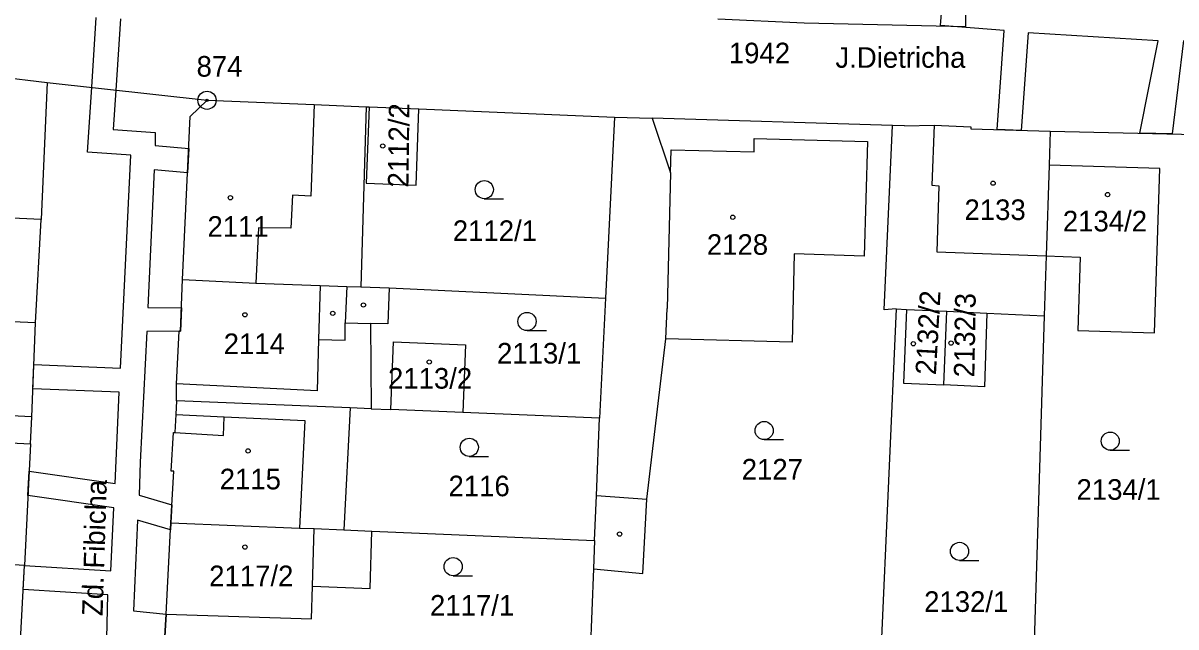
# Model space of a CAD drawing. Extents: x -755819 to -753140, y -1169796 to -1166000.
# Drawn here: x -755181.4 to -755086.2, y -1168037.7 to -1167987.9 of the extents above; entities that cross this region are included whole.
import ezdxf

# ---------------------------------------------------------------- set-up
doc = ezdxf.new("R2010")
doc.units = 0
for name, color, linetype in [('Vrstva 1', 7, 'Continuous'), ('Vrstva 15', 7, 'Continuous'), ('Vrstva 17', 7, 'Continuous'), ('Vrstva 18', 7, 'Continuous'), ('Vrstva 19', 7, 'Continuous'), ('Vrstva 24', 7, 'Continuous'), ('Vrstva 25', 7, 'Continuous'), ('Vrstva 27', 7, 'Continuous'), ('Vrstva 4', 7, 'Continuous')]:
    doc.layers.add(name, color=color, linetype=linetype)

msp = doc.modelspace()

# ---------------------------------------------------------------- linework, layer by layer
at = {"layer": 'Vrstva 1'}
for p, q in [((-755201.7, -1167990.2), (-755179.37, -1167992.78)), ((-755179.37, -1167992.78), (-755179.86, -1168004.09)), ((-755179.37, -1167992.78), (-755166.17, -1167994.26)), ((-755167.56, -1167995.59), (-755166.17, -1167994.26)), ((-755166.17, -1167994.26), (-755157.33, -1167994.61)), ((-755157.33, -1167994.61), (-755153.04, -1167994.79)), ((-755153.04, -1167994.79), (-755153.48, -1168009.65)), ((-755153.04, -1167994.79), (-755152.79, -1167994.8)), ((-755152.79, -1167994.8), (-755153.03, -1168001.11)), ((-755152.79, -1167994.8), (-755148.67, -1167994.97)), ((-755148.91, -1168001.27), (-755148.67, -1167994.97)), ((-755148.67, -1167994.97), (-755132.53, -1167995.65)), ((-755168.19, -1168009.04), (-755167.56, -1167995.59)), ((-755132.53, -1167995.65), (-755133.27, -1168010.58)), ((-755132.53, -1167995.65), (-755129.41, -1167995.74)), ((-755109.58, -1167996.35), (-755129.41, -1167995.74)), ((-755129.41, -1167995.74), (-755127.9, -1168000.25)), ((-755110.26, -1168011.56), (-755109.58, -1167996.35)), ((-755108.58, -1167996.38), (-755109.58, -1167996.35)), ((-755108.58, -1167996.38), (-755106.13, -1167996.31)), ((-755106.13, -1167996.31), (-755103.11, -1167996.46)), ((-755103.11, -1167996.46), (-755103.12, -1167996.61)), ((-755103.12, -1167996.61), (-755096.55, -1167996.81)), ((-755096.55, -1167996.81), (-755096.64, -1167999.6)), ((-755096.55, -1167996.81), (-755084.51, -1167997.07)), ((-755121, -1167998.52), (-755121, -1167997.4)), ((-755121, -1167997.4), (-755111.63, -1167997.67)), ((-755111.63, -1167997.67), (-755111.92, -1168007.11)), ((-755127.9, -1168000.25), (-755127.85, -1167998.34)), ((-755127.85, -1167998.34), (-755121, -1167998.52)), ((-755096.64, -1167999.6), (-755096.9, -1168007.1)), ((-755087.5, -1167999.9), (-755096.64, -1167999.6)), ((-755087.95, -1168013.46), (-755087.5, -1167999.9)), ((-755153.03, -1168001.11), (-755148.91, -1168001.27)), ((-755179.86, -1168004.09), (-755190.56, -1168003.61)), ((-755180.34, -1168012.62), (-755179.86, -1168004.09)), ((-755117.69, -1168006.93), (-755117.81, -1168011.73)), ((-755111.92, -1168007.11), (-755117.69, -1168006.93)), ((-755096.9, -1168007.1), (-755097.05, -1168012.04)), ((-755096.9, -1168007.1), (-755094.07, -1168007.19)), ((-755094.07, -1168007.19), (-755094.27, -1168013.25)), ((-755168.35, -1168013.31), (-755168.19, -1168009.04)), ((-755168.19, -1168009.04), (-755162.15, -1168009.34)), ((-755162.15, -1168009.34), (-755156.83, -1168009.53)), ((-755156.83, -1168009.53), (-755154.63, -1168009.62)), ((-755154.63, -1168009.62), (-755153.48, -1168009.65)), ((-755153.48, -1168009.65), (-755151.14, -1168009.73)), ((-755151.14, -1168009.73), (-755151.24, -1168012.71)), ((-755151.14, -1168009.73), (-755133.27, -1168010.58)), ((-755133.27, -1168010.58), (-755133.76, -1168020.48)), ((-755109.26, -1168011.47), (-755110.63, -1168041.69)), ((-755109.26, -1168011.47), (-755110.26, -1168011.56)), ((-755109.26, -1168011.47), (-755108.42, -1168011.51)), ((-755108.42, -1168011.51), (-755108.68, -1168017.61)), ((-755108.42, -1168011.51), (-755105.1, -1168011.66)), ((-755105.33, -1168017.75), (-755105.1, -1168011.66)), ((-755105.1, -1168011.66), (-755101.78, -1168011.82)), ((-755180.34, -1168012.62), (-755188.32, -1168012.28)), ((-755117.81, -1168011.73), (-755117.87, -1168014.23)), ((-755101.78, -1168011.82), (-755101.99, -1168017.89)), ((-755101.78, -1168011.82), (-755097.05, -1168012.04)), ((-755097.05, -1168012.04), (-755097.97, -1168042.2)), ((-755180.63, -1168020.37), (-755180.34, -1168012.62)), ((-755168.68, -1168017.65), (-755168.48, -1168013.31)), ((-755168.48, -1168013.31), (-755168.35, -1168013.31)), ((-755151.24, -1168012.71), (-755152.68, -1168012.67)), ((-755152.68, -1168012.67), (-755152.61, -1168019.71)), ((-755094.27, -1168013.25), (-755087.95, -1168013.46)), ((-755150.99, -1168019.77), (-755150.77, -1168014.19)), ((-755150.77, -1168014.19), (-755144.84, -1168014.43)), ((-755144.84, -1168014.43), (-755145.06, -1168020.01)), ((-755129.86, -1168027.18), (-755128.3, -1168013.95)), ((-755117.87, -1168014.23), (-755128.3, -1168013.95)), ((-755168.69, -1168019.05), (-755168.68, -1168017.65)), ((-755108.68, -1168017.61), (-755105.33, -1168017.75)), ((-755101.99, -1168017.89), (-755105.33, -1168017.75)), ((-755168.69, -1168019.05), (-755168.75, -1168020.19)), ((-755154.35, -1168019.64), (-755168.69, -1168019.05)), ((-755168.75, -1168020.19), (-755168.84, -1168021.67)), ((-755154.35, -1168019.64), (-755154.87, -1168029.71)), ((-755152.61, -1168019.71), (-755154.35, -1168019.64)), ((-755152.61, -1168019.71), (-755150.99, -1168019.77)), ((-755145.06, -1168020.01), (-755150.99, -1168019.77)), ((-755133.76, -1168020.48), (-755145.06, -1168020.01)), ((-755180.75, -1168022.61), (-755180.63, -1168020.37)), ((-755134.02, -1168026.88), (-755133.76, -1168020.48)), ((-755191.56, -1168022.09), (-755180.75, -1168022.61)), ((-755169.14, -1168024.85), (-755168.95, -1168021.67)), ((-755168.95, -1168021.67), (-755168.84, -1168021.67)), ((-755180.75, -1168022.61), (-755181.25, -1168032.65)), ((-755169.15, -1168029.11), (-755168.92, -1168024.85)), ((-755168.92, -1168024.85), (-755169.14, -1168024.85)), ((-755134.17, -1168030.57), (-755134.02, -1168026.88)), ((-755130.2, -1168033.31), (-755129.86, -1168027.18)), ((-755169.55, -1168036.67), (-755169.15, -1168029.11)), ((-755169.15, -1168029.11), (-755158.53, -1168029.55)), ((-755158.53, -1168029.55), (-755157.33, -1168029.6)), ((-755157.47, -1168034.35), (-755157.33, -1168029.6)), ((-755157.33, -1168029.6), (-755154.87, -1168029.71)), ((-755154.87, -1168029.71), (-755152.55, -1168029.8)), ((-755152.55, -1168029.8), (-755134.17, -1168030.57)), ((-755134.17, -1168030.57), (-755134.26, -1168032.92)), ((-755181.25, -1168032.65), (-755191.89, -1168031.99)), ((-755181.76, -1168042.63), (-755181.25, -1168032.65)), ((-755134.26, -1168032.92), (-755134.57, -1168040.46)), ((-755134.26, -1168032.92), (-755130.2, -1168033.31)), ((-755157.54, -1168037.03), (-755157.47, -1168034.35)), ((-755169.67, -1168038.95), (-755169.55, -1168036.67)), ((-755169.55, -1168036.67), (-755157.54, -1168037.03))]:
    msp.add_line(p, q, dxfattribs=at)
at = {"layer": 'Vrstva 24'}
for radius in [0.75, 0.1]:
    msp.add_circle((-755166.17, -1167994.26), radius, dxfattribs=at)
at = {"layer": 'Vrstva 25'}
for p, q in [((-755143.28, -1168002.38), (-755141.68, -1168002.38)), ((-755139.75, -1168013.26), (-755138.15, -1168013.26)), ((-755120.17, -1168022.26), (-755118.57, -1168022.26)), ((-755144.52, -1168023.64), (-755142.92, -1168023.64)), ((-755091.6, -1168023.13), (-755090, -1168023.13)), ((-755104.04, -1168032.23), (-755102.44, -1168032.23)), ((-755145.85, -1168033.49), (-755144.25, -1168033.49))]:
    msp.add_line(p, q, dxfattribs=at)
for centre, radius in [((-755151.66, -1167998.03), 0.175), ((-755143.28, -1168001.63), 0.75), ((-755101.27, -1168001.1), 0.175), ((-755164.24, -1168002.3), 0.175), ((-755091.82, -1168002.04), 0.175), ((-755122.76, -1168003.91), 0.175), ((-755153.26, -1168011.15), 0.175), ((-755163.04, -1168011.96), 0.175), ((-755155.79, -1168011.84), 0.175), ((-755139.75, -1168012.51), 0.75), ((-755107.86, -1168014.35), 0.175), ((-755104.74, -1168014.29), 0.175), ((-755147.82, -1168015.85), 0.175), ((-755120.17, -1168021.51), 0.75), ((-755091.6, -1168022.38), 0.75), ((-755162.78, -1168023.19), 0.175), ((-755144.52, -1168022.89), 0.75), ((-755132.11, -1168030.05), 0.175), ((-755163.04, -1168031.12), 0.175), ((-755104.04, -1168031.48), 0.75), ((-755145.85, -1168032.74), 0.75)]:
    msp.add_circle(centre, radius, dxfattribs=at)
at = {"layer": 'Vrstva 27'}
for p, q in [((-755105.6, -1167988.09), (-755105.46, -1167986.09)), ((-755103.51, -1167986.2), (-755103.55, -1167988.2)), ((-755175.69, -1167993.19), (-755175.32, -1167987.43)), ((-755173.32, -1167987.53), (-755173.7, -1167993.42)), ((-755116.88, -1167987.9), (-755123.99, -1167987.56)), ((-755103.55, -1167988.2), (-755116.88, -1167987.9)), ((-755100.37, -1167988.51), (-755105.6, -1167988.09)), ((-755100.94, -1167996.68), (-755100.37, -1167988.51)), ((-755098.37, -1167988.69), (-755098.94, -1167996.74)), ((-755087.65, -1167989.36), (-755098.37, -1167988.69)), ((-755089.15, -1167996.97), (-755087.65, -1167989.36)), ((-755085.55, -1167989.33), (-755086.5, -1167997.03)), ((-755176.03, -1167998.55), (-755175.69, -1167993.19)), ((-755173.7, -1167993.42), (-755173.91, -1167996.68)), ((-755173.91, -1167996.68), (-755170.45, -1167996.92)), ((-755170.45, -1167996.92), (-755170.46, -1167997.99)), ((-755098.94, -1167996.74), (-755100.94, -1167996.68)), ((-755086.5, -1167997.03), (-755089.15, -1167996.97)), ((-755170.46, -1167997.99), (-755167.68, -1167998.24)), ((-755167.68, -1167998.24), (-755167.78, -1168000.25)), ((-755172.47, -1167998.79), (-755176.03, -1167998.55)), ((-755173.3, -1168016.35), (-755172.47, -1167998.79)), ((-755170.52, -1168000), (-755171.06, -1168011.35)), ((-755167.78, -1168000.25), (-755170.52, -1168000)), ((-755171.06, -1168011.35), (-755168.28, -1168011.37)), ((-755168.28, -1168011.37), (-755168.35, -1168013.31)), ((-755171.14, -1168013.35), (-755171.7, -1168024.11)), ((-755168.48, -1168013.31), (-755171.14, -1168013.35)), ((-755168.35, -1168013.31), (-755168.48, -1168013.31)), ((-755180.54, -1168018.06), (-755180.47, -1168016.06)), ((-755180.47, -1168016.06), (-755173.3, -1168016.35)), ((-755173.41, -1168018.35), (-755180.54, -1168018.06)), ((-755173.76, -1168025.88), (-755173.41, -1168018.35)), ((-755180.96, -1168026.88), (-755180.86, -1168024.87)), ((-755180.86, -1168024.87), (-755173.76, -1168025.88)), ((-755171.7, -1168024.11), (-755171.78, -1168026.84)), ((-755173.87, -1168027.89), (-755180.96, -1168026.88)), ((-755171.78, -1168026.84), (-755169.07, -1168027.64)), ((-755169.07, -1168027.64), (-755169.15, -1168029.11)), ((-755174.11, -1168033.07), (-755173.87, -1168027.89)), ((-755171.91, -1168028.89), (-755172.25, -1168036.38)), ((-755169.18, -1168029.7), (-755171.91, -1168028.89)), ((-755169.15, -1168029.11), (-755169.18, -1168029.7)), ((-755181.35, -1168034.62), (-755181.25, -1168032.65)), ((-755181.25, -1168032.65), (-755174.11, -1168033.07)), ((-755174.36, -1168035.06), (-755181.35, -1168034.62)), ((-755174.51, -1168041.13), (-755174.36, -1168035.06)), ((-755172.25, -1168036.38), (-755169.55, -1168036.67)), ((-755169.55, -1168036.67), (-755169.67, -1168038.95))]:
    msp.add_line(p, q, dxfattribs=at)
at = {"layer": 'Vrstva 4'}
for p, q in [((-755157.33, -1167994.61), (-755157.61, -1168002.16)), ((-755106.13, -1167996.31), (-755106.32, -1168001.27)), ((-755127.9, -1168000.25), (-755128.19, -1168011.43)), ((-755159.1, -1168002.09), (-755159.26, -1168004.81)), ((-755157.61, -1168002.16), (-755159.1, -1168002.09)), ((-755106.32, -1168001.27), (-755105.74, -1168001.33)), ((-755105.74, -1168001.33), (-755105.92, -1168006.77)), ((-755161.91, -1168004.77), (-755162.15, -1168009.34)), ((-755159.26, -1168004.81), (-755161.91, -1168004.77)), ((-755105.92, -1168006.77), (-755096.9, -1168007.1)), ((-755156.83, -1168009.53), (-755156.96, -1168014)), ((-755154.63, -1168009.62), (-755154.76, -1168012.62)), ((-755128.3, -1168013.95), (-755128.19, -1168011.43)), ((-755154.77, -1168014.06), (-755154.76, -1168012.62)), ((-755154.76, -1168012.62), (-755152.68, -1168012.67)), ((-755156.96, -1168014), (-755157.07, -1168018.23)), ((-755156.96, -1168014), (-755154.77, -1168014.06)), ((-755157.07, -1168018.23), (-755168.68, -1168017.65)), ((-755180.63, -1168020.37), (-755190.09, -1168019.93)), ((-755168.75, -1168020.19), (-755164.75, -1168020.37)), ((-755164.82, -1168021.91), (-755164.75, -1168020.37)), ((-755164.75, -1168020.37), (-755158.1, -1168020.67)), ((-755158.1, -1168020.67), (-755158.53, -1168029.55)), ((-755168.84, -1168021.67), (-755164.82, -1168021.91)), ((-755134.02, -1168026.88), (-755129.86, -1168027.18)), ((-755152.71, -1168034.53), (-755152.55, -1168029.8)), ((-755157.47, -1168034.35), (-755152.71, -1168034.53))]:
    msp.add_line(p, q, dxfattribs=at)

# ---------------------------------------------------------------- texts
at = {"layer": 'Vrstva 15'}
msp.add_text('J.Dietricha', height=1.7, dxfattribs=at).set_placement((-755114.289, -1167991.58))
msp.add_text('Zd. Fibicha', height=1.7, rotation=88.17821, dxfattribs=at).set_placement((-755174.794, -1168036.834))
at = {"layer": 'Vrstva 17'}
msp.add_text('874', height=1.7, dxfattribs=at).set_placement((-755167.033, -1167992.31))
at = {"layer": 'Vrstva 18'}
for s, p in [('1942', (-755123.087, -1167991.21)), ('2112/1', (-755145.876, -1168005.87)), ('2113/1', (-755142.228, -1168015.98)), ('2127', (-755122.023, -1168025.55)), ('2116', (-755146.233, -1168026.93)), ('2134/1', (-755094.383, -1168027.22)), ('2117/1', (-755147.763, -1168036.78)), ('2132/1', (-755106.963, -1168036.47))]:
    msp.add_text(s, height=1.7, dxfattribs=at).set_placement(p)
at = {"layer": 'Vrstva 19'}
for s, rotation, p in [('2112/2', 89.26683, (-755149.541, -1168001.468)), ('2132/2', 86.80311, (-755105.991, -1168016.951)), ('2132/3', 89.03764, (-755102.817, -1168017.131))]:
    msp.add_text(s, height=1.7, rotation=rotation, dxfattribs=at).set_placement(p)
for s, p in [('2133', (-755103.633, -1168004.14)), ('2111', (-755166.133, -1168005.52)), ('2134/2', (-755095.513, -1168005.08)), ('2128', (-755124.903, -1168007.01)), ('2114', (-755164.793, -1168015.2)), ('2113/2', (-755151.23, -1168018.05)), ('2115', (-755165.123, -1168026.36)), ('2117/2', (-755165.993, -1168034.35))]:
    msp.add_text(s, height=1.7, dxfattribs=at).set_placement(p)

doc.saveas('drawing.dxf')
